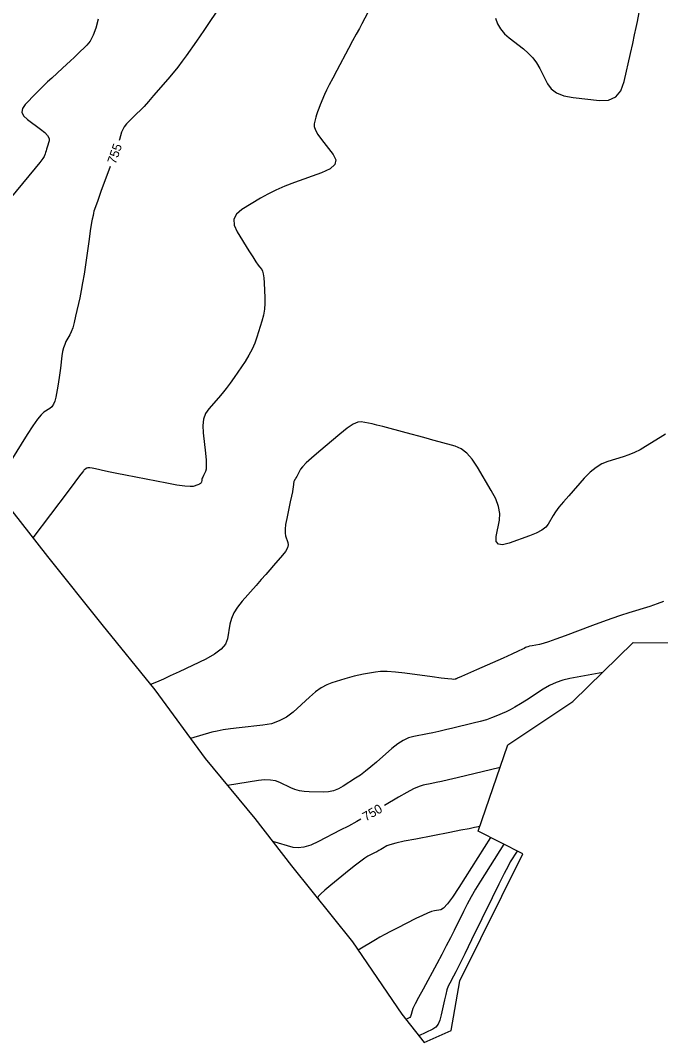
# Model space of a CAD drawing. Extents: x 2079879 to 2092887, y 778083 to 784051.
# Drawn here: x 2084032.2 to 2084229.6, y 780345.4 to 780660.6 of the extents above; entities that cross this region are included whole.
import ezdxf

# ---------------------------------------------------------------- set-up
doc = ezdxf.new("R2010")
doc.units = 0
for name, color, linetype in [('DT_X_Contour_Major', 7, 'Continuous'), ('DT_X_Contour_Minor', 7, 'Continuous'), ('DT_X_TIN_Hull', 7, 'Continuous')]:
    doc.layers.add(name, color=color, linetype=linetype)

msp = doc.modelspace()

# ---------------------------------------------------------------- linework, layer by layer
at = {"layer": 'DT_X_Contour_Major'}
for points in [[(2084093.48, 780664.5), (2084090.8, 780660.54), (2084089.77, 780659.03), (2084088.7, 780657.47), (2084087.59, 780655.86), (2084086.44, 780654.21), (2084083.32, 780649.72), (2084082.09, 780648.01), (2084080.74, 780646.24), (2084079.26, 780644.41), (2084077.67, 780642.52), (2084073.24, 780637.41), (2084071.68, 780635.63), (2084070.3, 780634.11), (2084069.11, 780632.85), (2084068.11, 780631.86), (2084065.7, 780629.56), (2084064.88, 780628.7), (2084064.22, 780627.84), (2084063.72, 780626.98), (2084063.38, 780626.13), (2084062.71, 780623.84), (2084062.61, 780623.53)], [(2084059.84, 780615.6), (2084057.01, 780607.82), (2084056.03, 780605.11), (2084055.31, 780603.09), (2084054.87, 780601.77), (2084054.69, 780601.15), (2084054.58, 780600.42), (2084054.54, 780600.16), (2084054.5, 780599.94), (2084054.45, 780599.76), (2084054.41, 780599.62), (2084054.3, 780599.3), (2084054.21, 780598.82), (2084054.02, 780597.63), (2084053.74, 780595.73), (2084053.36, 780593.12), (2084052.23, 780585.22), (2084051.8, 780582.36), (2084051.36, 780579.72), (2084050.92, 780577.28), (2084050.46, 780575.05), (2084049.22, 780569.4), (2084048.76, 780567.45), (2084048.31, 780565.83), (2084047.86, 780564.55), (2084047.42, 780563.61), (2084046.24, 780561.55), (2084045.84, 780560.7), (2084045.49, 780559.68), (2084045.21, 780558.49), (2084045, 780557.14), (2084044.51, 780553.32), (2084044.32, 780551.91), (2084044.12, 780550.52), (2084043.91, 780549.17), (2084043.68, 780547.86), (2084043.07, 780544.38), (2084042.78, 780543.19), (2084042.38, 780542.22), (2084041.86, 780541.46), (2084041.23, 780540.92), (2084039.39, 780539.77), (2084038.55, 780539.01), (2084037.42, 780537.61), (2084035.98, 780535.56), (2084034.24, 780532.87), (2084029.22, 780524.81)], [(2084180.11, 780430.25), (2084166.81, 780427.05), (2084164.19, 780426.42), (2084162.03, 780425.92), (2084160.32, 780425.54), (2084159.07, 780425.28), (2084156.34, 780424.75), (2084155.1, 780424.37), (2084153.42, 780423.64), (2084151.3, 780422.54), (2084148.74, 780421.08), (2084144.43, 780418.53)], [(2084137.17, 780414.3), (2084135.92, 780413.6), (2084133.31, 780412.17), (2084130.76, 780410.84), (2084124.06, 780407.39), (2084121.69, 780406.31), (2084119.61, 780405.65), (2084117.82, 780405.4), (2084116.33, 780405.57), (2084110.02, 780407.35)]]:
    msp.add_lwpolyline(points, dxfattribs=at)
at = {"layer": 'DT_X_Contour_Minor'}
for points in [[(2084139.32, 780663.07), (2084137.46, 780659.58), (2084136.68, 780658.12), (2084135.73, 780656.35), (2084134.62, 780654.28), (2084133.34, 780651.9), (2084129.71, 780645.14), (2084128.46, 780642.78), (2084127.42, 780640.75), (2084126.59, 780639.07), (2084125.98, 780637.72), (2084124.64, 780634.57), (2084124.17, 780633.45), (2084123.78, 780632.43), (2084123.48, 780631.53), (2084123.25, 780630.73), (2084122.74, 780628.76), (2084122.74, 780627.9), (2084123.13, 780626.79), (2084123.9, 780625.44), (2084125.05, 780623.85), (2084128.64, 780619.28), (2084129.42, 780617.64), (2084129.09, 780616.15), (2084127.64, 780614.8), (2084125.06, 780613.61), (2084116.71, 780610.62), (2084113.7, 780609.47), (2084110.94, 780608.28), (2084108.44, 780607.05), (2084106.18, 780605.77), (2084100.5, 780602.3), (2084098.8, 780600.89), (2084097.99, 780599.27), (2084098.04, 780597.42), (2084098.98, 780595.36), (2084102.63, 780589.58), (2084103.86, 780587.65), (2084104.82, 780586.17), (2084105.49, 780585.16), (2084105.9, 780584.61), (2084106.6, 780583.76), (2084106.84, 780583.27), (2084107.04, 780582.42), (2084107.2, 780581.22), (2084107.32, 780579.66), (2084107.58, 780575.05), (2084107.59, 780573.3), (2084107.44, 780571.52), (2084107.12, 780569.71), (2084106.63, 780567.86), (2084105.11, 780562.91), (2084104.46, 780561.05), (2084103.63, 780559.19), (2084102.62, 780557.33), (2084101.44, 780555.47), (2084098.07, 780550.52), (2084096.82, 780548.73), (2084095.61, 780547.08), (2084094.42, 780545.58), (2084093.27, 780544.22), (2084090.25, 780540.78), (2084089.29, 780539.36), (2084088.68, 780537.66), (2084088.42, 780535.7), (2084088.51, 780533.46), (2084089.23, 780527.14), (2084089.43, 780525), (2084089.5, 780523.35), (2084089.45, 780522.17), (2084089.27, 780521.47), (2084088.62, 780520.23), (2084088.4, 780519.8), (2084088.24, 780519.42), (2084088.14, 780519.11), (2084088.09, 780518.85), (2084088.03, 780518.24), (2084087.95, 780518.02), (2084087.73, 780517.8), (2084087.39, 780517.6), (2084086.91, 780517.41), (2084085.47, 780516.91), (2084084.55, 780516.83), (2084082.88, 780516.97), (2084080.46, 780517.33), (2084077.29, 780517.91), (2084067.81, 780519.75), (2084064.56, 780520.39), (2084061.91, 780520.91), (2084059.86, 780521.32), (2084058.41, 780521.62), (2084055.35, 780522.28), (2084054.32, 780522.48), (2084053.54, 780522.59), (2084052.99, 780522.6), (2084052.68, 780522.53), (2084052.17, 780522.21), (2084052, 780522.1), (2084051.87, 780522.01), (2084051.78, 780521.93), (2084051.72, 780521.87), (2084051.64, 780521.74), (2084051.32, 780521.31), (2084050.43, 780520.12), (2084048.96, 780518.17), (2084046.91, 780515.46), (2084036.03, 780501.05)], [(2084178.62, 780661.29), (2084179.28, 780659.56), (2084180.21, 780657.97), (2084181.42, 780656.51), (2084182.91, 780655.19), (2084187.25, 780651.85), (2084188.78, 780650.53), (2084190.13, 780649.09), (2084191.3, 780647.51), (2084192.28, 780645.81), (2084194.65, 780641.1), (2084195.81, 780639.51), (2084197.51, 780638.27), (2084199.77, 780637.39), (2084202.57, 780636.86), (2084210.77, 780635.93), (2084213.55, 780636.03), (2084215.74, 780637.03), (2084217.35, 780638.94), (2084218.36, 780641.75), (2084220.28, 780650.44), (2084220.96, 780653.5), (2084221.53, 780656.17), (2084222.02, 780658.43), (2084222.4, 780660.3), (2084223.31, 780664.74)], [(2084056.12, 780660.95), (2084055.39, 780658.24), (2084054.57, 780656.01), (2084053.66, 780654.25), (2084052.65, 780652.98), (2084049.82, 780650.22), (2084048.73, 780649.17), (2084047.6, 780648.1), (2084046.42, 780646.99), (2084045.18, 780645.86), (2084041.83, 780642.79), (2084040.58, 780641.63), (2084039.34, 780640.45), (2084038.12, 780639.24), (2084036.91, 780638.02), (2084033.69, 780634.71), (2084032.83, 780633.49), (2084032.65, 780632.31), (2084033.15, 780631.15), (2084034.33, 780630.03), (2084038.39, 780627.09), (2084039.69, 780626.03), (2084040.57, 780625.08), (2084041.01, 780624.22), (2084041.01, 780623.46), (2084040.46, 780621.57), (2084040.26, 780620.91), (2084040.08, 780620.34), (2084039.93, 780619.88), (2084039.8, 780619.5), (2084039.49, 780618.64), (2084039.11, 780618.02), (2084038.2, 780616.82), (2084036.77, 780615.04), (2084034.82, 780612.66), (2084028.91, 780605.56)], [(2084231.08, 780533.03), (2084229.41, 780531.96), (2084224.96, 780529.19), (2084223.28, 780528.22), (2084221.56, 780527.37), (2084219.82, 780526.64), (2084218.04, 780526.04), (2084213.26, 780524.59), (2084211.46, 780523.87), (2084209.66, 780522.76), (2084207.86, 780521.29), (2084206.05, 780519.44), (2084201.23, 780514.02), (2084199.58, 780512.11), (2084198.23, 780510.46), (2084197.2, 780509.08), (2084196.47, 780507.95), (2084194.95, 780505.29), (2084194.16, 780504.31), (2084192.93, 780503.38), (2084191.25, 780502.48), (2084189.13, 780501.63), (2084182.88, 780499.4), (2084180.87, 780498.91), (2084179.54, 780499.09), (2084178.88, 780499.96), (2084178.9, 780501.5), (2084179.86, 780506.52), (2084179.97, 780508.5), (2084179.59, 780510.69), (2084178.73, 780513.07), (2084177.37, 780515.66), (2084173.11, 780522.85), (2084171.48, 780525.27), (2084169.79, 780527.14), (2084168.03, 780528.48), (2084166.21, 780529.26), (2084161.27, 780530.64), (2084159.34, 780531.18), (2084157.27, 780531.75), (2084155.05, 780532.35), (2084152.68, 780532.99), (2084146.16, 780534.75), (2084143.91, 780535.35), (2084142.06, 780535.82), (2084140.61, 780536.17), (2084139.55, 780536.4), (2084137.25, 780536.85), (2084136.19, 780536.74), (2084134.74, 780536.07), (2084132.89, 780534.85), (2084130.65, 780533.06), (2084124.15, 780527.55), (2084121.97, 780525.66), (2084120.32, 780524.14), (2084119.19, 780522.98), (2084118.59, 780522.18), (2084117.68, 780520.53), (2084117.37, 780519.97), (2084117.13, 780519.53), (2084116.95, 780519.2), (2084116.83, 780518.98), (2084116.61, 780518.56), (2084116.53, 780518.37), (2084116.46, 780518.15), (2084116.41, 780517.89), (2084116.38, 780517.58), (2084116.3, 780516.7), (2084116.22, 780516.17), (2084116.04, 780515.23), (2084115.77, 780513.9), (2084115.4, 780512.16), (2084114.29, 780506.98), (2084113.95, 780505.19), (2084113.79, 780503.69), (2084113.79, 780502.5), (2084113.96, 780501.61), (2084114.63, 780499.63), (2084114.72, 780498.83), (2084114.49, 780497.91), (2084113.93, 780496.87), (2084113.04, 780495.72), (2084110.24, 780492.48), (2084109.12, 780491.19), (2084107.86, 780489.75), (2084106.45, 780488.14), (2084104.9, 780486.39), (2084100.57, 780481.5), (2084099.12, 780479.68), (2084098, 780477.9), (2084097.22, 780476.16), (2084096.77, 780474.45), (2084096.03, 780469.93), (2084095.41, 780468.27), (2084094.08, 780466.67), (2084092.05, 780465.12), (2084089.33, 780463.63), (2084081.13, 780459.73), (2084078.39, 780458.44), (2084076.31, 780457.47), (2084074.91, 780456.82), (2084074.17, 780456.51), (2084072.28, 780455.78)], [(2084230.45, 780481.4), (2084228.5, 780480.65), (2084226.23, 780479.89), (2084219.73, 780477.86), (2084217.21, 780477.05), (2084214.51, 780476.13), (2084211.62, 780475.11), (2084208.56, 780473.98), (2084200.16, 780470.85), (2084197.3, 780469.8), (2084195.01, 780469), (2084193.31, 780468.46), (2084192.18, 780468.18), (2084189.94, 780467.75), (2084189.18, 780467.6), (2084188.6, 780467.46), (2084188.18, 780467.33), (2084187.92, 780467.22), (2084187.47, 780466.93), (2084186.94, 780466.66), (2084185.68, 780466.08), (2084183.69, 780465.18), (2084180.98, 780463.96), (2084172.78, 780460.3), (2084170.08, 780459.1), (2084168.15, 780458.24), (2084166.99, 780457.72), (2084166.59, 780457.54), (2084166.54, 780457.53), (2084166.51, 780457.52), (2084166.44, 780457.51), (2084166.34, 780457.49), (2084166.19, 780457.46), (2084165.77, 780457.38), (2084165.24, 780457.41), (2084163.95, 780457.55), (2084161.92, 780457.81), (2084159.14, 780458.18), (2084150.71, 780459.32), (2084147.78, 780459.66), (2084145.29, 780459.83), (2084143.24, 780459.83), (2084141.63, 780459.66), (2084137.95, 780458.97), (2084136.55, 780458.69), (2084135.12, 780458.36), (2084133.67, 780457.98), (2084132.18, 780457.55), (2084128.17, 780456.33), (2084126.62, 780455.72), (2084124.96, 780454.78), (2084123.2, 780453.52), (2084121.35, 780451.94), (2084116.26, 780447.31), (2084114.24, 780445.75), (2084112.01, 780444.56), (2084109.58, 780443.72), (2084106.93, 780443.25), (2084099.58, 780442.47), (2084097, 780442.16), (2084094.74, 780441.82), (2084092.82, 780441.46), (2084091.23, 780441.07), (2084084.6, 780439.16)], [(2084211.73, 780459.56), (2084201.6, 780457.64), (2084199.45, 780457.13), (2084197.37, 780456.4), (2084195.34, 780455.47), (2084193.36, 780454.32), (2084188.17, 780450.98), (2084186.32, 780449.82), (2084184.66, 780448.84), (2084183.2, 780448.04), (2084181.92, 780447.43), (2084178.79, 780446.03), (2084177.47, 780445.5), (2084175.86, 780444.96), (2084173.95, 780444.4), (2084171.76, 780443.84), (2084165.51, 780442.32), (2084163.26, 780441.79), (2084161.21, 780441.32), (2084159.35, 780440.92), (2084157.67, 780440.6), (2084153.47, 780439.81), (2084151.87, 780439.36), (2084150.21, 780438.58), (2084148.51, 780437.49), (2084146.75, 780436.07), (2084142, 780431.87), (2084140.25, 780430.38), (2084138.6, 780429.05), (2084137.03, 780427.88), (2084135.54, 780426.88), (2084131.68, 780424.41), (2084130.22, 780423.61), (2084128.71, 780423.04), (2084127.16, 780422.71), (2084125.56, 780422.61), (2084121.26, 780422.67), (2084119.69, 780422.76), (2084118.21, 780423.01), (2084116.81, 780423.4), (2084115.51, 780423.93), (2084112.15, 780425.57), (2084110.79, 780426.06), (2084109.24, 780426.33), (2084107.49, 780426.36), (2084105.55, 780426.16), (2084096.02, 780424.71)], [(2084173.83, 780412.04), (2084172.83, 780411.8), (2084172.15, 780411.66), (2084170.54, 780411.34), (2084168.01, 780410.85), (2084164.54, 780410.18), (2084154.06, 780408.15), (2084150.55, 780407.45), (2084147.91, 780406.86), (2084146.12, 780406.39), (2084145.18, 780406.03), (2084143.84, 780405.24), (2084143.3, 780404.93), (2084142.7, 780404.6), (2084142.04, 780404.24), (2084141.32, 780403.86), (2084139.3, 780402.83), (2084138.37, 780402.27), (2084137.11, 780401.37), (2084135.5, 780400.14), (2084133.56, 780398.57), (2084127.92, 780393.94), (2084126.08, 780392.4), (2084124.79, 780391.25), (2084124.04, 780390.5), (2084123.84, 780390.14), (2084124.18, 780389.39)], [(2084177.1, 780408.64), (2084167.35, 780393.18), (2084165.44, 780390.26), (2084163.86, 780388.15), (2084162.64, 780386.84), (2084161.76, 780386.33), (2084159.87, 780386.04), (2084158.98, 780385.81), (2084157.73, 780385.33), (2084156.11, 780384.6), (2084154.12, 780383.63), (2084148.35, 780380.7), (2084146.31, 780379.65), (2084144.52, 780378.7), (2084142.98, 780377.86), (2084141.7, 780377.11), (2084136.31, 780373.88)], [(2084181.22, 780406.54), (2084174.01, 780395.11), (2084172.53, 780392.69), (2084171.16, 780390.33), (2084169.91, 780388.04), (2084168.77, 780385.81), (2084165.91, 780379.94), (2084164.77, 780377.65), (2084163.5, 780375.18), (2084162.1, 780372.53), (2084160.57, 780369.7), (2084156.31, 780361.9), (2084154.91, 780359.29), (2084153.88, 780357.3), (2084153.22, 780355.94), (2084152.94, 780355.2), (2084152.71, 780354.07), (2084152.6, 780353.68), (2084152.46, 780353.38), (2084152.29, 780353.15), (2084152.08, 780353.01), (2084151.03, 780352.53)], [(2084185.35, 780404.44), (2084183.22, 780401.07), (2084182.52, 780399.83), (2084181.35, 780397.57), (2084179.71, 780394.28), (2084177.59, 780389.97), (2084171.31, 780377.11), (2084169.19, 780372.79), (2084167.56, 780369.47), (2084166.4, 780367.16), (2084165.72, 780365.85), (2084164.55, 780363.7), (2084164.12, 780362.78), (2084163.7, 780361.62), (2084163.31, 780360.21), (2084162.94, 780358.58), (2084161.96, 780353.89), (2084161.53, 780352.29), (2084160.95, 780351.03), (2084160.23, 780350.11), (2084159.37, 780349.51), (2084155.01, 780347.51)]]:
    msp.add_lwpolyline(points, dxfattribs=at)
at = {"layer": 'DT_X_TIN_Hull'}
msp.add_lwpolyline([(2084024.28, 780515.97), (2084040.54, 780495.32), (2084057.24, 780474.3), (2084073.63, 780454.12), (2084089.16, 780432.95), (2084104.51, 780414.51), (2084115.75, 780399.9), (2084134.58, 780376.43), (2084149.76, 780354.13), (2084156.7, 780345.39), (2084164.98, 780349.14), (2084167.68, 780364.39), (2084187.07, 780403.56), (2084173.32, 780410.56), (2084182.51, 780437.21), (2084202.54, 780450.58), (2084221.09, 780468.71), (2084252.85, 780468.7)], dxfattribs=at)

# ---------------------------------------------------------------- texts
at = {"layer": 'DT_X_Contour_Major'}
for s, rotation, p in [('755', 70.6899, (2084061.53, 780616.11)), ('750', 30.2134, (2084138.68, 780413.53))]:
    msp.add_text(s, height=2.8, rotation=rotation, dxfattribs=at).set_placement(p)

doc.saveas('drawing.dxf')
